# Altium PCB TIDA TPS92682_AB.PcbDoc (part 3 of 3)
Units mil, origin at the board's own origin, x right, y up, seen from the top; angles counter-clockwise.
Board outline 3149 x 2999 mil, 6 copper layers (Top Layer, Signal Layer 1, Signal Layer 2, Signal Layer 3, Signal Layer 4, Bottom Layer), stack 61.4 mil thick; 281 components, 181 nets, 796 pads, 814 vias.
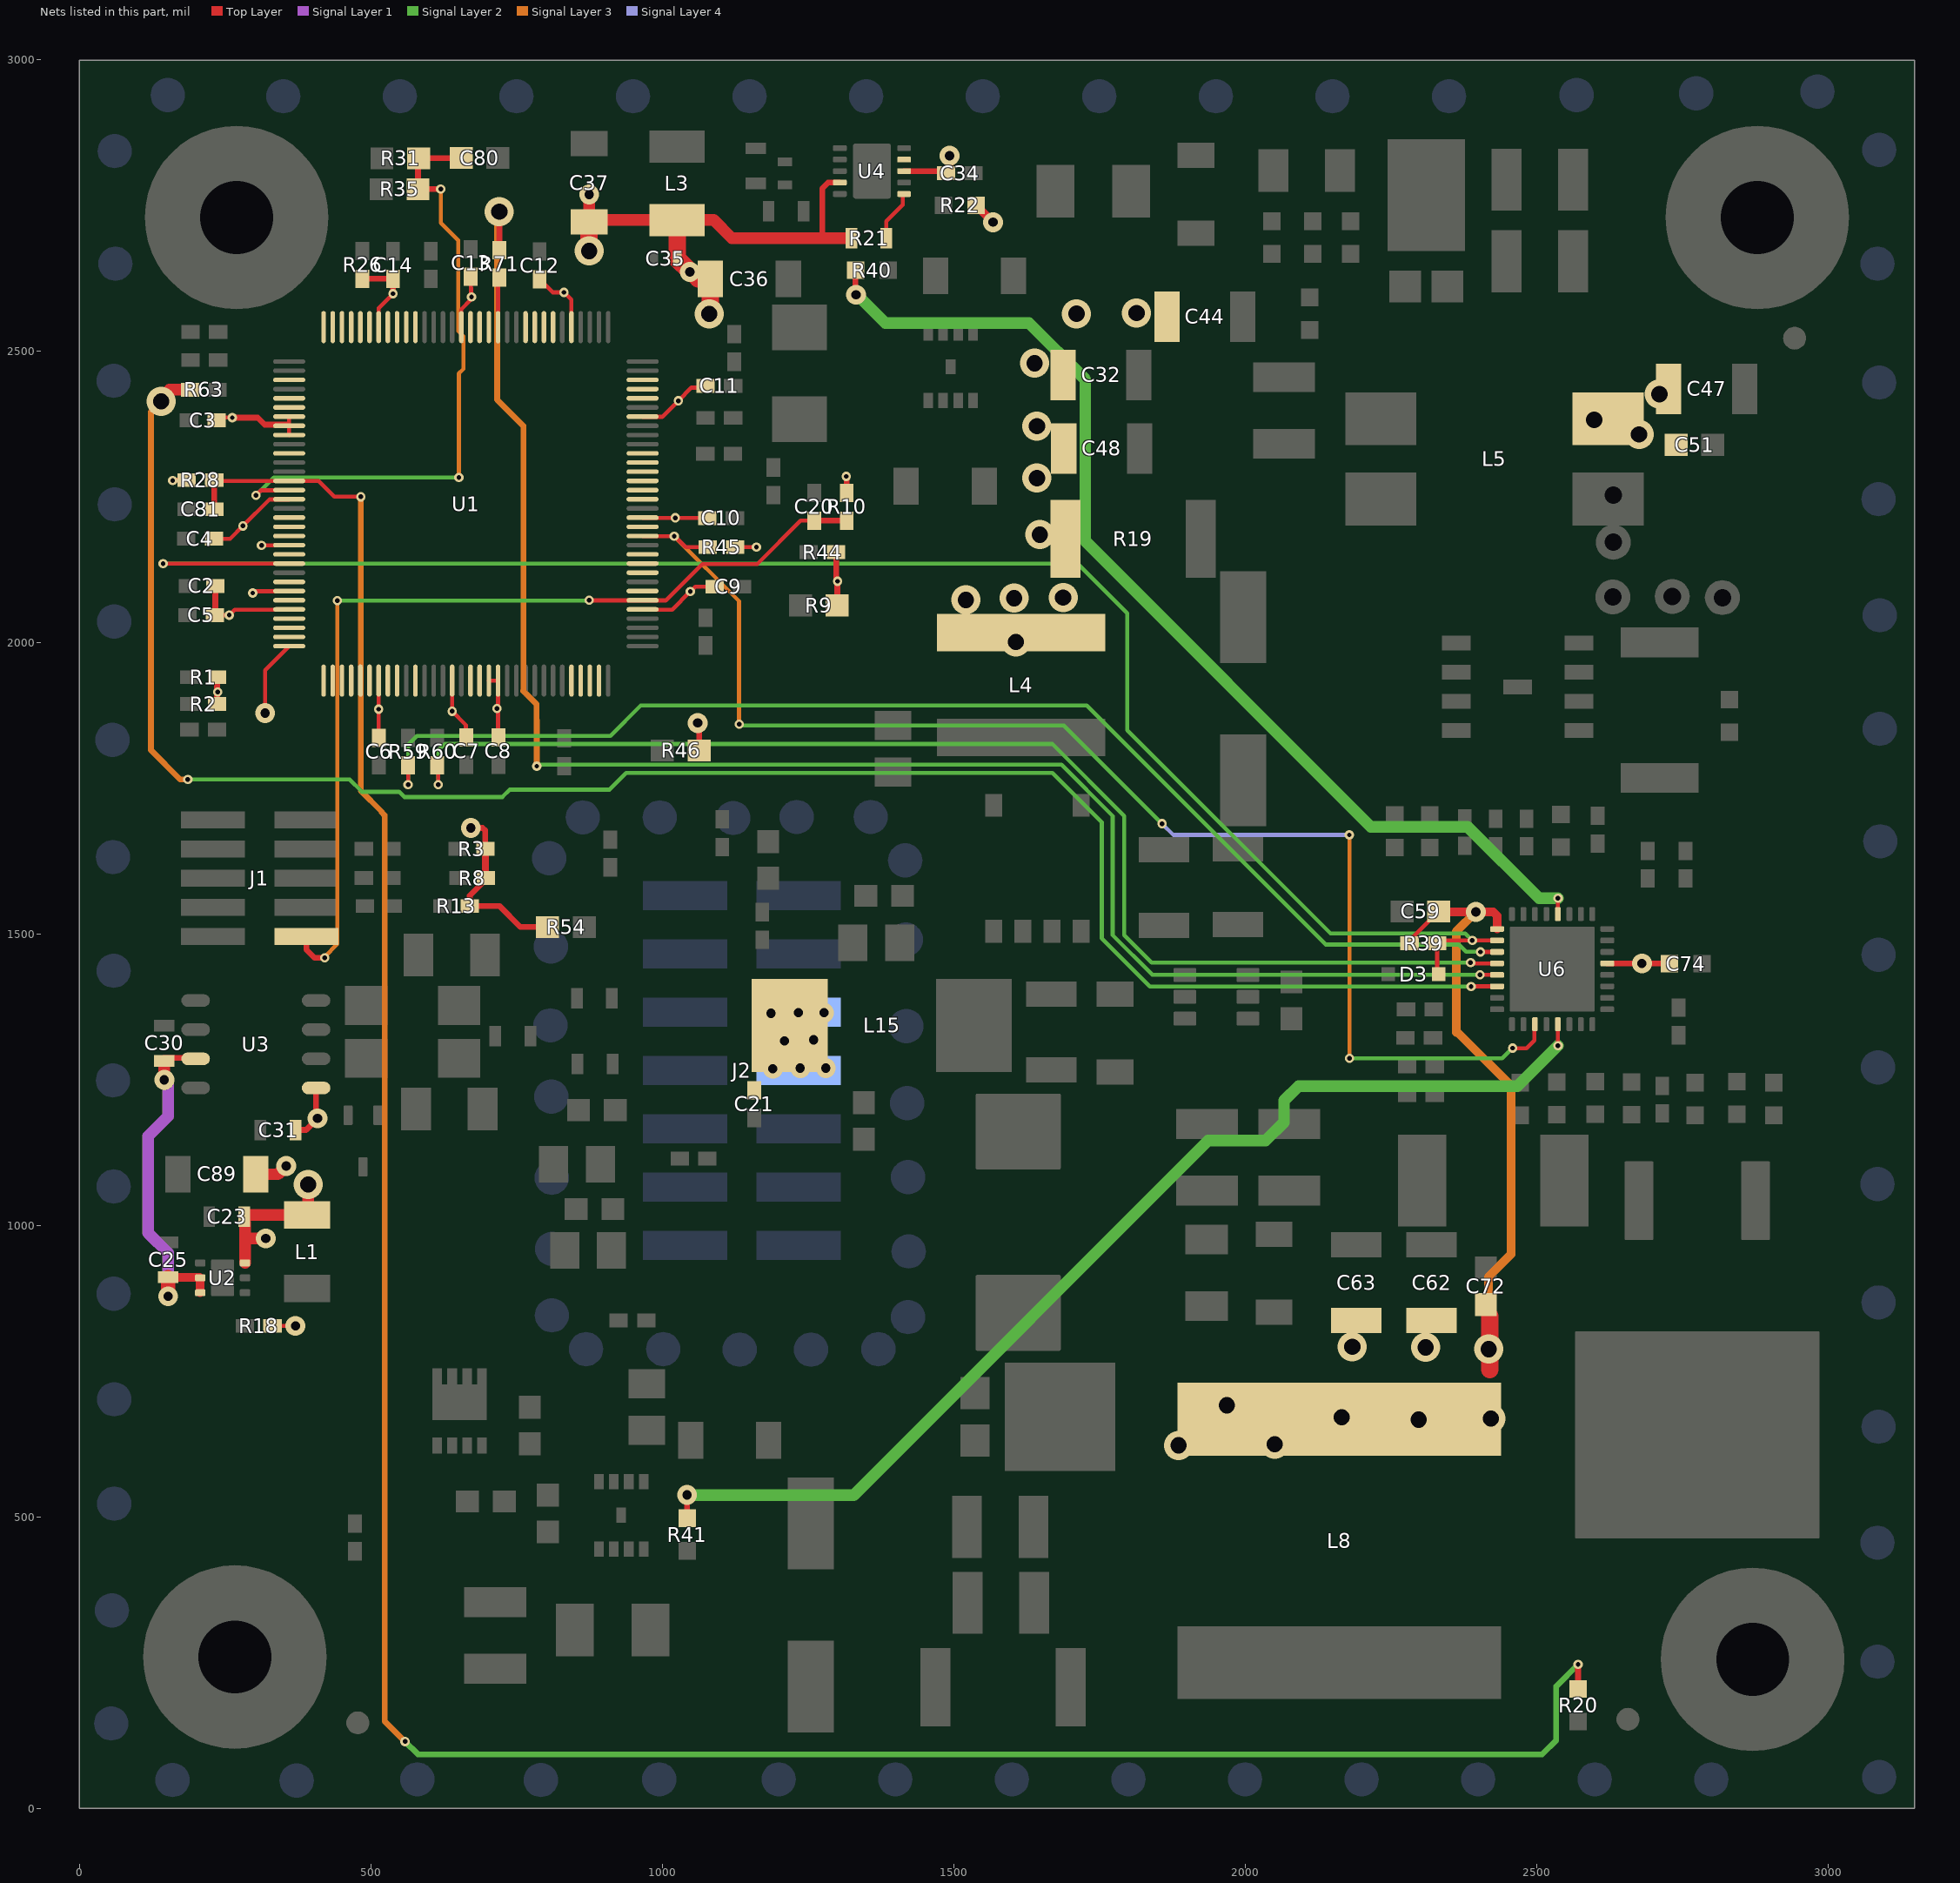
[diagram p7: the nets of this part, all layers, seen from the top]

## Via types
v1: diameter 16, hole 8, Top Layer to Bottom Layer, tented both sides, 458 vias
v2: diameter 50, hole 28, Top Layer to Bottom Layer, tented both sides, 188 vias
v3: diameter 34, hole 16, Top Layer to Bottom Layer, tented both sides, 85 vias
v4: diameter 16, hole 8, Top Layer to Bottom Layer, 33 vias
v5: diameter 34, hole 16, Top Layer to Bottom Layer, tented bottom, 30 vias
v6: diameter 19.68, hole 7.87, Top Layer to Bottom Layer, 18 vias
v7: diameter 34, hole 16, Top Layer to Bottom Layer, 2 vias

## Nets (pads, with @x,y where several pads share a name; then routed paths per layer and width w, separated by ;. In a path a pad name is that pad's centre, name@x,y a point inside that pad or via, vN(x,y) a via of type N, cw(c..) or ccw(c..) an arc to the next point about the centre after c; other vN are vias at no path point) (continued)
nFLT2: R45.1 U1.77 U6.11 | length 2358.5
  Top Layer w7: U1.77@966.49,2182.37 v1(1020.76,2182.37) 1022.02,2182.37 1040.76,2163.63 R45.1@1078.14,2163.63 ; v1@2459,1306.8 v1(2459,1304.4) 2459.4,1304 2483.08,1304 2496.68,1317.61 U6.11@2496.68,1345.27
  Signal Layer 2 w7: v1@1132,1857.68 1689.32,1857.68 v1(1857.69,1689.31) ; v1(2179.39,1287) 2179.67,1286.72 2441.32,1286.72 v1(2459,1304.4)
  Signal Layer 3 w7: v1(1020.76,2182.37) 1132,2071.13 v1@1132,1857.68 ; v1(2179.39,1287) v1@2179.39,1670
  Signal Layer 4 w7: v1(1857.69,1689.31) 1877,1670 v1(2179,1670)
  other v1: 1132.18,1859.96
nRST: R21.2 U4.6 | length 88.1
  Top Layer w7: R21.2@1384.76,2693.63 1384.76,2722.63 1412.76,2750.63 1412.76,2767.14 U4.6@1414.88,2769.26
PA2: U1.35
PA3: U1.36
PA4: U1.37
PA5: U1.38
PA6: U1.40
PA7: U1.41
PB3: U1.92
PB4: U1.121
PB5: U1.120
PC7: U1.22
PCB_Temp: C81.1 R20.2 R28.1 U1.14 | length 4664.4
  Top Layer w7: R28.1@231.58,2276.86 360.19,2276.86 410.59,2276.86 437.45,2250 v1(483,2250) ; R28.1@231.58,2278.67 R28.1@234.02,2276.23
  Top Layer w10: C81.1@231.58,2228.67 R28.1@231.58,2278.67 ; R20.2@2571.49,205.33 v1(2571.49,247.33)
  Signal Layer 2 w10: v1(559,115) 581,93 2510,93 2534,117 2534,209.84 v1(2571.49,247.33)
  Signal Layer 3 w10: v1(483,2250) 483,1746 519,1710 519,1708.72 524,1703.72 524,150 v1(559,115)
PD2: U1.3
PD4: U1.125
PD5: U1.126
PD6: U1.127
PD7: U1.128
PDRV1: R40.2 U6.28 | length 1864.9
  Top Layer w7: v3@1331.76,2597.63 v3(1332.76,2596.63) ; U6.28@2536.84,1534.25 v1@2536.84,1561.34
  Top Layer w10: v3@1331.76,2597.63 R40.2@1331.76,2638.63
  Signal Layer 2 w20: v3(1332.76,2596.63) 1334.37,2596.63 1383,2548 1629.4,2548 1726,2451.4 1726,2174.15 2216.15,1684 2382,1684 2504.5,1561.5 v1(2537,1561.5)
PDRV2: R41.2 U6.13 | length 1912.2
  Top Layer w7: U6.13@2536.78,1345.21 U6.13@2536.84,1345.27 2537,1345.11 v1(2537,1308.5)
  Top Layer w10: v3(1042.79,538) 1043,537.79 R41.2@1043,498
  Signal Layer 2 w20: v3(1042.79,538) 1043,537.79 1329,537.79 1936.97,1145.76 2035.41,1145.76 2067,1177.34 2067,1214.22 2091.78,1239 2467.5,1239 v1(2537,1308.5)
PE4: U1.123
PE5: U1.124
PF1: U1.43
PG0: U1.49
PG1: U1.50
PH0: U1.29
PH1: U1.30
PH2: U1.31
PH3: U1.32 | length 131.5
  Top Layer w7: v5(319,1879) 319,1952.21 U1.32@360.19,1993.39
PK0: U1.18
PK1: U1.19
PK2: U1.20
PK3: U1.21 | length 47.4
  Top Layer w7: v1(312.76,2166.63) U1.21@360.19,2166.62
PK4: U1.63
PK5: U1.62
PK6: U1.61
PK7: U1.60
PL0: U1.81
PL1: U1.82
PL2: U1.83
PL3: U1.84
PL4: U1.85
PL5: U1.86
PL6: U1.94
PL7: U1.93
PM0: U1.78
PM3: U1.75
PM4: U1.74
PM5: U1.73
PM7: U1.71
PN3: U1.110
PN4: U1.111
PN5: U1.112
POS_EN: U1.25
PP0: U1.118
PP1: U1.119
PP2: U1.103
PP3: U1.104
PP4: U1.105
PP5: U1.106
PQ0: U1.5
PQ1: U1.6
PQ2: U1.11
PQ3: U1.27
PWM1: R59.2 U6.3 | length 2173.5
  Top Layer w7: v1(564.23,1756) R59.2@564.23,1789.45 ; v1(2404,1469.29) U6.3@2432.51,1469.29
  Signal Layer 2 w7: v1(564.23,1756) 564.23,1824.88 579.35,1840 911.31,1840 963.31,1892 1728.3,1892 2138.3,1482 2366.84,1482 2379.34,1469.5 2403.79,1469.5 v1(2404,1469.29)
PWM2: R60.2 U6.4 | length 2189.8
  Top Layer w7: R60.2@614.23,1789.45 616,1787.68 v1(616,1756) ; v1(2387,1451) 2388.4,1449.6 U6.4@2432.51,1449.6
  Signal Layer 2 w7: v1(616,1756) 616,1814.84 627.16,1826 1669.33,1826 1793,1702.33 1793,1498 1840,1451 v1(2387,1451)
RST_N: C20.1 J1.10 R10.1 U1.70 | length 1612.7
  Top Layer w7: v1(874.76,2072.63) 875.25,2072.13 1006.26,2072.13 1068.76,2134.63 1163.33,2134.63 1237.8,2209.1 C20.1@1261,2209.1
  Top Layer w10: J1.10@389.7,1495.64 389.7,1473.3 404,1459 v1(421.03,1459) ; C20.1@1261,2209.1 R10.1@1316.73,2209.1
  Signal Layer 2 w7: v1(443,2072) 874.13,2072 v1(874.76,2072.63)
  Signal Layer 3 w7: v1(421.03,1459) 421.03,1461.03 443,1483 v1(443,2072)
SCLK: R63.1 U6.6 | length 3302
  Top Layer w7: v1@2388.23,1410.23 U6.6@2432.51,1410.23
  Top Layer w10: R63.1@185.89,2435.63 R63.1@190.96,2440.7
  Top Layer w20: v2(140.76,2413.63) 140.76,2419.63 154.76,2433.63 R63.1@190.14,2433.63
  Signal Layer 2 w7: v1(186.38,1765) 464,1765 485,1744 549,1744 558,1735 726,1735 738.5,1747.5 909.5,1747.5 938.5,1776.5 1669.5,1776.5 1754.24,1691.76 1754.24,1492.76 1837,1410 v1(2388,1410)
  Signal Layer 3 w10: v2(140.76,2413.63) 123,2395.87 123,1815.48 173.48,1765 v1(186.38,1765)
SSN: R71.1 U6.5 | length 2964.6
  Top Layer w7: v1(2403,1430) U6.5@2432.51,1429.92
  Top Layer w10: R71.1@720.76,2673.25 v2(720.76,2739)
  Signal Layer 2 w7: v1(785,1788) 787.5,1790.5 1685.03,1790.5 1773,1702.53 1773,1498 1841,1430 v1(2403,1430)
  Signal Layer 3 w10: v2(720.76,2739) 717,2735.24 717,2416.45 762,2371.45 762,1917 761.67,1917 784.76,1893.91 784.76,1867.24 785,1867 v1(785,1788)
SSN_1: R71.2 U1.109 | length 86.3
  Top Layer w7: U1.109@718.45,2540.64 718.45,2623.7 R71.2@720.76,2626.01
Sync: U4.9
TPS_EN: D3.1 R39.2 U1.23 U6.2 | length 3011.3
  Top Layer w7: v1@144,2135.13 U1.23@360.19,2135.13 ; v1(144,2135.35) v1@144.48,2136.52 ; D3.1@2329.62,1427.68 D3.1@2332.31,1425 ; D3.1@2332.31,1431 2329.62,1433.68 R39.2@2329.62,1484 2334.59,1488.97 U6.2@2432.51,1488.97
  Signal Layer 2 w7: v1(144,2135.35) 1712.65,2135.35 1798.1,2049.9 1798.1,1849.77 2146.87,1501 2378,1501 v1(2390,1489)
UART_0_RX: U1.33
UART_0_TX: U1.34
V3p3: C2.1 C3.1 C4.1 C5.1 C6.1 C7.1 C8.1 C9.1 C10.1 C11.1 C12.1 C13.1 C14.1 C23.1 C31.1 C35.1 C36.1 C37.1 C89.1 L1.1 L3.2 R1.2 R2.2 R3.2 R8.2 R9.1 R10.2 R13.2 R18.2 R21.1 R26.2 R28.2 R44.2 R45.2 R46.2 R54.2 U1.7 U1.8 U1.9 U1.16 U1.26 U1.28 U1.39 U1.47 U1.51 U1.52 U1.69 U1.79 U1.90 U1.101 U1.113 U1.122 U2.6 U3.5 U4.4 | length 3666.6
  Top Layer w7: C4.1@231,2178 258.85,2178 v1(280.85,2200) 326.21,2245.36 U1.16@360.19,2245.36 ; C5.1@233,2047 v1(257.38,2047) 266.76,2056.39 360.19,2056.39 U1.28@359.94,2056.63 ; C2.1@233,2095 233.62,2095.62 C2.1@241,2103 ; C3.1@236.96,2384.49 238.5,2386.03 305.76,2386.03 ; v1(297.69,2085) 300.58,2087.88 U1.26@360.19,2087.88 ; R18.2@331.62,828 v3(371,828) ; U1.9@360.19,2355.6 360.19,2371.35 U1.7@360.19,2386.03 ; C6.1@513.73,1836.09 v1(513.73,1885.72) U1.39@513.73,1934.34 ; U1.122@513.73,2540.64 513.73,2573.67 v1(538.34,2598.28) ; U1.47@639.71,1934.34 v1(639.71,1882.11) 663.34,1858.49 663.34,1838.08 C7.1@664.11,1837.31 ; U1.113@655.46,2540.64 655.46,2571.46 672.24,2588.24 672.18,2592.67 C13.1@671.76,2627.2 ; U1.51@702.71,1934.34 718.45,1934.34 v1@718.45,1887.63 ; v1(716.76,1886.63) 717.76,1887.63 v1@718.45,1887.63 ; C8.1@718.45,1835.82 v1@718.45,1887.63 ; C12.1@789.76,2623.2 812.32,2600.63 v1(831.76,2600.63) 844.44,2587.95 U1.101@844.44,2540.64 ; U1.69@966.49,2056.39 1017.23,2056.39 v1(1048.34,2087.49) 1048.62,2087.49 1056.76,2095.63 C9.1@1090.14,2095.63 ; U1.79@966.49,2213.87 v1(1022.76,2213.87) 1077.34,2213.87 C10.1@1077.71,2213.49 ; U1.90@966.49,2387.09 1000.17,2387.09 v1(1027.73,2414.66) 1050.34,2437.27 C11.1@1071.72,2437.27 ; R45.2@1125.38,2163.63 v1(1161.76,2163.63)
  Top Layer w8: v1@163.71,2278.67 R28.2@184.33,2278.67
  Top Layer w10: R28.2@183.38,2279.63 R28.2@184.33,2278.67 ; C5.1@233,2047 233.62,2047.62 233.62,2095.62 C2.1@233.62,2097 ; R2.2@236.38,1894.63 R1.2@236.38,1940.63 ; v1(262.55,2385.63) 305.76,2385.63 ; C23.1@281,1008 280.85,1008.15 280.85,1019.86 C23.1@282.71,1017.99 ; 305.76,2386.03 318.16,2373.63 357.9,2373.63 U1.8@360.19,2371.35 ; v3@355,1094.01 v3(355,1102) ; C31.1@371,1164 389.32,1164 v3(409,1183.68) 406.35,1186.34 U3.5@406.35,1236 ; R26.2@485.76,2624.01 538.2,2624.01 C14.1@538.34,2623.87 v1(538.34,2598.28) ; R13.2@671.74,1549.12 673.88,1551.26 R13.2@676.02,1549.12 ; v3(672,1682) 692,1682 696.67,1677.33 R3.2@696.67,1646 ; R8.2@697.67,1596 697.67,1593.44 670.12,1565.89 R13.2@670.12,1548.12 720.88,1548.12 756.95,1512.05 R54.2@803.5,1512.05 ; v5(1061,1862) 1063.5,1859.5 R46.2@1063.5,1815 ; 1275.76,2693.63 1274.76,2694.63 1274.76,2778.63 1285.07,2788.94 U4.4@1304.64,2788.94 ; v1@1298.62,2107.38 R44.2@1298.62,2155 ; R9.1@1300.5,2063.63 v1@1300.5,2105.5 ; v1(1316,2285) 1316.76,2284.24 R10.2@1316.76,2256.31
  Top Layer w12: C23.1@281,1008 C23.1@284.39,1004.61 ; R8.2@695.67,1594 696.67,1595 R3.2@696.67,1646
  Top Layer w20: C23.1@282.71,1017.99 L1.1@391,1017.99 ; U2.6@284.39,935.87 284.39,978 ; C23.1@284.39,1004.61 284.39,978 ; C89.1@303,1088 341,1088 v3(355,1102) ; v7(320,978) 284.39,978 ; L1.1@393,1017.99 v2(393,1070.5) ; v3(874.76,2768.63) C37.1@874.76,2721.7 877.69,2724.64 L3.2@1025.76,2724.64 1088.75,2724.64 1119.76,2693.63 1275.76,2693.63 R21.1@1324.76,2693.63 ; C36.1@1061.76,2623.63 C36.1@1082.83,2623.63 ; v2(1080.76,2563.63) 1080.76,2569.63 v2@1082.83,2571.7
  Top Layer w30: v2(874.76,2671.63) C37.1@874.76,2721.7 ; C35.1@1024.76,2658.63 v3(1047.76,2635.63) ; C35.1@1025.76,2659.63 L3.2@1025.76,2724.64 ; C35.1@1026.57,2658.81 C36.1@1061.76,2623.63 ; v2@1082.83,2571.7 C36.1@1082.83,2623.63
  other v1: 237.76,1915.13 1301,2105 160.38,2278 673.08,2592.68
V5p0: C25.1 C30.1 U2.2 U2.3 U3.3 | length 603.7
  Top Layer w10: C30.1@145.58,1282.64 150.58,1287.64 U3.3@199.65,1287.64
  Top Layer w15: C25.1@152.42,911.36 U2.2@206.53,911.36 ; U2.3@207.61,884.69 U2.2@207.61,910.28
  Top Layer w20: C30.1@145.58,1282.64 146,1282.22 v3(146,1250)
  Top Layer w25: v3(152.42,878.58) C25.1@152.42,911.36
  Signal Layer 1 w10: v3(146,1250) v3@152.42,1243.58
  Signal Layer 1 w20: v3(152.42,878.58) 152.42,953.28 118.42,987.28 118.42,1153.42 152.42,1187.42 v3@152.42,1243.58
VBATT_Filt: C32.1 C34.1 C44.1 C47.1 C48.1 C51.2 C59.2 C62.1 C63.1 C72.2 L4.2 L5.2 L8.1 R19.2 R22.2 R39.1 U4.8 U6.1 | length 1264
  Top Layer w7: R39.1@2282.38,1484 2282.38,1488.88 C59.2@2332.5,1539 C59.2@2333.54,1537.96
  Top Layer w10: U4.8@1415.12,2808.63 1483.41,2808.63 C34.1@1487.14,2804.9
  Top Layer w12: C34.1@1487.14,2804.9 1493,2810.75 v3(1493,2835) ; R22.2@1538.76,2749.9 R22.2@1538.76,2753.27
  Top Layer w15: R22.2@1538.76,2749.9 v3(1567.76,2720.9) ; C59.2@2333.54,1537.96 v3(2396,1537.96) 2425.84,1537.96 2432.51,1531.29 U6.1@2432.51,1508.66
  Top Layer w30: 2420,753 2420,844.5
  Signal Layer 3 w15: v3(2396,1537.96) 2362.23,1504.19 2362.23,1331.12 2364.88,1331.12 2456.38,1239.62 2456.38,950.92 2418,912.54 v2(2418,788)
  other v2: 1886,623 2051,625 2298,667 2422,669 2166,671 1969,691.83 2310,791 2184,792 1607,2001 1521,2073 1604,2076 1688,2077 1648,2185 1643,2282 2676,2357 1643,2371 2599,2382 2711,2426 1639,2479 1711,2564 1814,2565
VCC: C74.1 U6.21 | length 110.3
  Top Layer w10: U6.21@2621.49,1449.6 2689,1449.6 2729.1,1449.6 C74.1@2731,1451.5
  other v3: 2681,1449.6
VIN+: C21.1 J2.5 J2.7 L15.1
  other v3: 1190,1269 1237,1270 1281,1270 1210.07,1316.68 1260.07,1318.68 1187,1364 1234,1365 1278,1365
VIN_ADC: C80.2 R31.1 R35.2 U1.15 | length 1100.5
  Top Layer w7: v1(303.48,2252.63) 311.96,2261.11 U1.15@360.19,2261.11
  Top Layer w10: v1(620.2,2777.63) R35.2@581.25,2777.63 581.25,2829.63 R31.1@582.25,2830.63 655.09,2830.63 C80.2@655.46,2831
  Signal Layer 2 w7: v1(303.48,2252.63) 333.85,2283 v1(651.37,2283)
  Signal Layer 3 w7: v1(620.2,2777.63) 620.2,2719.91 650.1,2690.01 650.1,2687 650.1,2534.23 659.27,2525.07 659.27,2469.27 651.37,2461.37 v1(651.37,2283)
pads on no net: Designator11.1@3090,1659 Designator12.1@3089,1852 Designator13.1@3087,1464.56 Designator14.1@1418.83,1342 Designator15.1@1418,1490.38 Designator16.1@1417,1626.19 Designator17.1@1357.92,1700.69 Designator18.1@1231,1700.69 Designator19.1@1121.96,1699 Designator20.1@996,1700.02 Designator21.1@864,1700.02 Designator22.1@806.26,1630 Designator23.1@809.14,1478.5 Designator24.1@808.42,1343.32 Designator25.1@810,1221 Designator26.1@810.69,1082 Designator27.1@811.52,960 Designator28.1@811,846 Designator29.1@869.45,788 Designator30.1@1002,788 Designator31.1@1133,787.2 Designator32.1@1255.46,787.2 Designator33.1@1371,788 Designator34.1@1422,843 Designator35.1@1423,955.7 Designator36.1@1422,1083 Designator37.1@1420.48,1210 Designator38.1@3088,54 Designator39.1@3085,252 Designator40.1@3085,456 Designator41.1@3087,654.98 Designator42.1@3087,868 Designator43.1@3085,1071.26 Designator44.1@3086,1271.24 Designator45.1@3089,2046.76 Designator46.1@3087,2246 Designator47.1@3088,2446 Designator48.1@3085,2649.81 Designator49.1@3088,2845 Designator50.1@2982,2945 Designator51.1@2774,2942 Designator52.1@2568.87,2939 Designator53.1@2350,2937 Designator54.1@2150,2937 Designator55.1@1950,2937 Designator56.1@1750,2937 Designator57.1@1550,2937 Designator58.1@1350,2937 Designator59.1@1150,2937 Designator60.1@950,2937 Designator61.1@750,2937 Designator62.1@550,2937 Designator63.1@350,2937 Designator64.1@152,2939 Designator65.1@61,2843 Designator66.1@62,2649.81 Designator67.1@59,2449 Designator68.1@61,2237 Designator69.1@60,2036 Designator70.1@57,1833 Designator71.1@58,1632 Designator72.1@59,1437 Designator73.1@58,1249 Designator74.1@59,1067 Designator75.1@59,883 Designator76.1@60,702 Designator77.1@60,523 Designator78.1@56,340 Designator79.1@55,146 Designator80.1@160,49 Designator81.1@373,48 Designator82.1@580,50 Designator83.1@791.94,49 Designator84.1@995,50 Designator85.1@1200,50 Designator86.1@1400,50 Designator87.1@1600,50 Designator88.1@1800,50 Designator89.1@2000,50 Designator90.1@2200,50 Designator91.1@2400,50 Designator92.1@2600,50 Designator93.1@2800,50 FID1.1 FID2.1 FID3.1 J1.7 LBL1.0 U1.65 U1.67 U1.72 U1.102 U2.7@246,892.57 U2.7@246,928 U4.11@1350.16,2748.39 U4.11@1350.16,2868.87 U4.11@1360,2783.83 U4.11@1360,2833.43 U4.11@1369.84,2748.39 U4.11@1369.84,2868.87

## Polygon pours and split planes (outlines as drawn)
GND on Top Layer "Top Layer-No Net 27" (solid, pour order 220): 2537,2601 2630,2508 2734.42,2508 2797.45,2444.97 2797.45,2294 2555.83,2294 2555.83,2034 2619.26,2034 2639.26,2014 2640,2014 2640,1941 2642,1939 2644,1941 2805,1941 2922,1941 2922,2441.85 2639.26,2742.81 2639.26,2847.15 2588.85,2847.15 2537,2847.15
NetC61_2 on Top Layer "Top Layer-NetC61_2" (solid, pour order 302): 1563,1012.71 1760,1012.71 1760,767 1582,767 1582,294.87 1494.36,294.87 1434.11,353.68 1339.97,353.68 1216.69,353.68 1216.69,571.1 1450.76,761.11 1450.76,1012.71
NetC78_1 on Top Layer "Top Layer-NetC78_1" (solid, pour order 298): 606,668 606,673 606,990.43 860,990.43 860,926 787,926 716.76,855.76 716.76,789.24 793,713 792,712 792,668
LB_ANODE on Top Layer "LB_ANODE" (solid, pour order 260): 973,990.01 1013.37,990.01 1114.93,990.01 1114.93,823.52 1040.5,823.52 1040.5,701.01 943.58,701.01 943.58,869.21 973,898.63
NetC40_2 on Top Layer "Top Layer-NetC40_2" (solid, pour order 284): 1503,1264.94 1600,1264.8 1600,1357 1817,1357 1817,1418.89 1684,1418.89 1684,1523.5 1503,1523.5
DRL+ on Top Layer "Top Layer-DRL+" (solid, pour order 290): 1159,1538.22 1159,1545 1159,1623 1218,1623 1240,1645 1240,1805 1431.5,1805 1431.5,1613.05 1306,1613.05 1306,1538.22
DRL- on Top Layer "Top Layer-DRL-" (solid, pour order 288): 1160.54,1440 1357,1440 1357,1577 1330,1577 1330,1519 1299.5,1519 1299.5,1499 1160,1499
NetC42_1 on Top Layer "Top Layer-NetC42_1" (solid, pour order 286): 1499,1562.18 1754,1562.18 1754,1613 1986,1613 2030,1613 2030,1671 1816.62,1671 1761,1726.62 1761,1869 1499,1869
VIN+ on Top Layer "Top Layer-VIN+" (solid, pour order 282): 1146,1423 1146,1230 1306,1230 1306,1423
NetC56_1 on Top Layer "Top Layer-NetC56_1" (solid, pour order 266): 1570,2496 1570,2397.47 1550.84,2378.32 1456.31,2378.31 1443,2365 1443,1834.72 1365.27,1834.72 1361,2496
GND on Top Layer "Top Layer-GND 1" (solid, pour order 276): 674.32,640 674.32,506.3 540.19,506.3 538.34,506.3 535.55,506.3 535.55,640
no net on Top Layer "Top Layer-No Net 2" (solid, pour order 274): 568.5,637
HB_LB_TAP on Top Layer "Top Layer-HB_LB_TAP" (solid, pour order 272): 966,1092.29 967.05,1092.29 1113,1092.29 1113,1032.29 978.25,1032.29 952.49,990.95 952.49,940.01 930.78,918.3 886,918.3 886,1046.5 912.5,1046.5 958.29,1092.29
HB_CATHODE on Top Layer "Top Layer-HB_CATHODE" (solid, pour order 270): 862,1072.91 862,1145 895,1145 895,1219 1112,1219 1112,1136 975.88,1136 917,1072.91
NetC64_1 on Top Layer "Top Layer-No Net" (solid, pour order 76): 2999,897.83 2999,131.78 1610,131.78 1610,556 1856,556 2476,556 2476,897.83
NetC70_1 on Top Layer "TOP_LAYER_NETC70_1_P156" (solid, remove dead copper, pour order 156): 855,673 855,483 1005,483 1005,573 1071,573 1071,673
no net on Top Layer "Top Layer-No Net 9" (solid, pour order 248): 491.69,394
NetC41_1 on Top Layer "Top Layer-No Net 16" (solid, pour order 198): 1959,1962.54 1959,2047.22 1898,2108.22 1898,2244.92 1949,2244.92 2054.54,2134.63 2054.54,1962.54
VBATT_Filt on Top Layer "Top Layer-No Net 15" (solid, pour order 178): 1472,1970 1760,1970 1760,2502 1776,2518 1885,2518 1885,2602 1882,2605 1881,2604 1687,2604 1601,2518 1601,2111 1472,2111
NetQ3_1 on Top Layer "Top Layer-No Net 23" (solid, pour order 144): 2548,1760 2551,1760 2766,1760 2766,1827 2766,1828 2766,1829 2766,1839 2661,1839 2598,1902 2598,1962 2548,1962
NetC69_1 on Top Layer "Top Layer-No Net 17" (solid, pour order 130): 951,458 951,390.39 929.59,362 894,362 894,261 797,261 797,328 657,328 657,428.84 854.43,428.84 883.59,458
NetC67_2 on Top Layer "Top Layer-No Net 10" (solid, pour order 108): 1715,895.61 1874.46,1085 2129,1085 2129,1022 1974.38,1022 1974.38,912 1885,912 1835.05,841.85 1835.05,579.43 1715,579.43
VBATT_Filt on Top Layer "Top Layer-No Net 1" (solid, pour order 78): 1860,744 1860,584 2456,584 2456,865 2138,865 2138,744
NetQ7_3 on Top Layer "Top Layer-No Net 3" (solid, pour order 82): 2507,1128 2507,972.36 2766,972.36 2766,1128
NetC49_2 on Top Layer "Top Layer-No Net 6" (solid, pour order 88): 2011,2394 2168,2394 2168,2338 2375,2338 2375,2639 2248,2639 2248,2584 2145,2481 2011,2481
NetC53_2 on Top Layer "Top Layer-No Net 7" (solid, pour order 90): 2475,2865 2475,2592.28 2390.72,2592.28 2390.72,2661 2220,2661 2220,2694 2090,2694 2090,2775 2090,2865
VBATT_Filt on Top Layer "Top Layer-No Net 8" (solid, pour order 94): 2559,2432 2640,2432 2681,2473 2754,2473 2754,2319 2560,2319 2559,2318
NetC49_1 on Top Layer "Top Layer-No Net 5" (solid, pour order 116): 2014,2367 2015,2366 2120.13,2366 2120.13,2313 2350,2313 2519.54,2313 2519.54,1776 2171,1776 2171,2049.9 2014,2212.56
NetC55_2 on Top Layer "Top Layer-No Net 14" (solid, pour order 118): 1473,2517.26 1565,2517.26 1565,2579 1473,2579
NetC78_2 on Top Layer "TOP_LAYER_NETC78_2_P158" (solid, remove dead copper, pour order 158): 687,651 794,651 807,638 807,598 829.7,575.3 829.7,511 771,511 756,496 719,496 719,546 687,578
V3p3 on Top Layer "TOP_LAYER_V3P3_P162" (solid, remove dead copper, pour order 162): 325.36,2386.63 324.76,2386.03 324.76,2356.47 328.6,2352.63 390.76,2352.63 390.76,2386.63
GND on Top Layer "Top Layer-No Net 24" (solid, pour order 166): 1327.43,2762.6 1391.51,2762.24 1392.24,2762.96 1392.24,2888 1327.43,2888
NetC85_1 on Top Layer "Top Layer-No Net 26" (solid, pour order 188): 1884,877 1884,770 2089,770 2089,878 1883,878
GND on Top Layer "Top Layer-GND" (solid, pour order 304): 1513,1235 1624,1235 2193.66,1235 2236.66,1192 2429,1192 2429,939.28 2147.64,939.28 2018,939.28 2018,1007 2018,1009.8 2018.8,1009.8 2151.04,1009.8 2151.04,1135 1830.29,1135 1758.9,1032.34 1513,1032.34
GND on Top Layer "Top Layer-GND 2" (solid, pour order 306): 1146.07,1193.5 1312,1193.5 1312,941 1150,941 1148,943
GND on Signal Layer 1 "SIGNAL_LAYER_1_GND_P330" (solid, remove dead copper, pour order 330): -7,2996 -4,2999 3137,2999 3137,7 3140,4 3,4
V3p3 on Signal Layer 1 "Signal Layer 1-V3p3" (solid, pour order 324): 115.01,2898 1418.83,2898 1418.83,1764.48 1374.79,1764.48 715,1764.48 715,717.37 721.37,711 940,711 940,92 115.01,92
NetC49_1 on Signal Layer 1 "Signal Layer 1-NetC49_1" (solid, pour order 308): 2014,2365.59 2014.41,2366 2120.13,2366 2120.13,2313 2519.54,2313 2519.54,1776 2171,1776 2171,2049.9 2014,2212.56
NetC85_1 on Signal Layer 1 "SIGNAL_LAYER_1_NETC85_1_P146" (solid, remove dead copper, pour order 146): 2122,888.03 1556.01,888.03 1063.98,396 941,396 941,210 1058.55,210 1613.55,765 2122,765
NetC64_1 on Signal Layer 1 "Signal Layer 1-No Net" (solid, pour order 190): 1630,556 1639,556 2472,556 2472,928 2472,1101 3034,1101 3034,90 2975,90 1608,90 1608,556
GND on Signal Layer 2 "SIGNAL_LAYER_2_GND_P332" (solid, remove dead copper, pour order 332): 21,0 3140,0 3149,9 3149,2999 0,2999
NetC49_1 on Signal Layer 2 "Top Layer-No Net 5" (solid, pour order 206): 2014,2366 2019,2366 2120.13,2366 2120.13,2313 2350,2313 2519.54,2313 2519.54,1772 2170.83,1772 2170.83,1955 2170.83,2049.9 2014,2212.56
NetC64_1 on Signal Layer 2 "Signal Layer 2-No Net" (solid, pour order 192): 1610,556 2471.19,556 2471.19,1100 3033,1100 3033,90 1634,90 1610,90
no net on Signal Layer 2 "Signal Layer 2-No Net 1" (solid, pour order 316): 1154,1399
GND on Signal Layer 3 "SIGNAL_LAYER_3_GND_P342" (solid, remove dead copper, pour order 342): 0,2999 3149,2999 3149,0 0,0
VBATT_Filt on Signal Layer 3 "SIGNAL_LAYER_3_VBATT_FILT_P340" (solid, remove dead copper, pour order 340): 1435,2909 1435,1295.24 1433,1293.24 3042,1293.24 3042,2909
NetC64_1 on Signal Layer 3 "Signal Layer 3-No Net" (solid, pour order 194): 1634,556 2472,556 2472,1101 3034,1101 3034,91 1610,91 1610,556
NetC49_1 on Signal Layer 3 "Top Layer-No Net 5" (solid, pour order 204): 2014,2367 2015,2366 2120.13,2366 2120.13,2313 2350,2313 2519.54,2313 2519.54,1776 2170,1776 2170,2049.9 2014,2212.56
GND on Signal Layer 4 "SIGNAL_LAYER_4_GND_P336" (solid, remove dead copper, pour order 336): 0,-7 0,2999 3149,2999 3149,9 3144,4
NetC64_1 on Signal Layer 4 "Signal Layer 4-No Net" (solid, pour order 196): 1610,556 2472,556 2472,1101 3034,1101 3034,91 1610,91
NetC49_1 on Signal Layer 4 "Top Layer-No Net 5" (solid, pour order 208): 2014,2367 2015,2366 2120.13,2366 2120.13,2313 2350,2313 2519.54,2313 2519.54,1776 2171,1776 2171,1948 2171,2049.9 2014,2212.56
GND on Bottom Layer "BOTTOM_LAYER_GND_P338" (solid, remove dead copper, pour order 338): 0,2999 3149,2999 3149,5 3144,0 3137,7 7,7
NetC64_1 on Bottom Layer "Top Layer-No Net" (solid, pour order 200): 3009,1101 3009,127 1610,127 1610,556 1856,556 2471.19,556 2471.19,1101
NetC49_1 on Bottom Layer "Top Layer-No Net 5" (solid, pour order 202): 2014,2367 2015,2366 2120.13,2366 2120.13,2313 2350,2313 2519.54,2313 2519.54,1782 2519.54,1776 2170,1776 2170,2049.9 2014,2212.56
VIN+ on Bottom Layer "Bottom Layer-VIN+" (solid, pour order 320): 1161.76,1390 1304.5,1390 1306,1391.5 1307.24,1390.26 1307.24,1242 1163,1242 1161.76,1243.24
no net on M1 Board Outline (solid): 384.99,781.24

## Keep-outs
Keep-Out Layer:
  text ".Layer_Name" at -282,-949.49 h60

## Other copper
Top Layer:
  rectangle net GND: 1612.88,1244.5 1855.39,1332
  rectangle net GND: 1818,1491.68 2101.24,1594
  rectangle net NetC56_1: 1361.21,2404 1571,2496.75
  rectangle net NetC70_1: 854,484 1006,584
  rectangle net GND: 10,2900 3135,2987
  rectangle net GND: 10,11 3135,86
  region net GND: 3135,18 3135,2980 3040,2980 3040,18
  region net GND: 107,25 107,2987 10,2987 10,25
  rectangle net V3p3: 1029.43,2593 1104.29,2656.04
  rectangle net GND: 1445,2596.91 1497,2708
  region net NetC42_1: 1594,1697.62
  pour cut-out: 494,391
  text ".Layer_Name" at -282,-949.49 h60
Signal Layer 1:
  rectangle net NetC67_2: 1626.48,574 1829,758
  rectangle net NetC53_2: 2233.12,2661 2390.72,2865.61
Signal Layer 2:
  rectangle net NetC67_2: 1626.48,574 1829,758
  rectangle net NetC53_2: 2233.12,2661 2390.72,2865.61
Signal Layer 3:
  rectangle net NetC67_2: 1626.48,574 1829,758
  rectangle net NetC53_2: 2233.12,2661 2390.72,2865.61
Signal Layer 4:
  rectangle net NetC67_2: 1626.48,574 1829,758
  rectangle net NetC53_2: 2233.12,2661 2390.72,2865.61
Bottom Layer:
  rectangle net NetC67_2: 1626.48,574 1829,758
  rectangle net NetC53_2: 2233.12,2661 2390.72,2865.61
  rectangle net GND: 10,11 3135,86
  region net GND: 3135,18 3135,2980 3046,2980 3046,18
  region net GND: 104,25 104,2987 10,2987 10,25
  rectangle net GND: 10,2900 3135,2987
  rectangle net GND: 749.59,734 879.59,1742
  rectangle net GND: 1357,734 1487,1743
  rectangle net GND: 749.59,734 1473,838
  rectangle net GND: 749.59,1639 1473,1743
  text ".Layer_Name" at -282,-949.49 h60

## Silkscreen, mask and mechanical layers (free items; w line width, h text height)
Top Overlay:
  text "1" at 217,1745 h50
  text "10" at 402.61,1418.93 h50
  text ".Layer_Name" at -282,-949.49 h60
Bottom Overlay:
  text "TIDA-050029" at 2428,710 h72.83
  text ".Layer_Name" at -282,-949.49 h60
Top Paste:
  text ".Layer_Name" at -282,-949.49 h60
Bottom Paste:
  text ".Layer_Name" at -282,-949.49 h60
Top Solder:
  text ".Layer_Name" at -282,-949.49 h60
  text ".Layer_Name" at -282,-949.49 h60
Bottom Solder:
  text ".Layer_Name" at -282,-949.49 h60
Drill Guide:
  text ".Layer_Name" at -282,-949.49 h60
M1 Board Outline:
  the board outline again, w10
  text ".Layer_Name" at -282,-949.49 h60
M2 Board Dimensions:
  rectangle: -734,-491 -359,-366
  rectangle: -859,-366 -734,-241
  lines w7: -859,-366 141,-366 ; -734,-491 -734,-241 ; -609,-491 -609,-241 ; -359,-491 -359,-241 ; -109,-491 -109,-241 ; -859,-491 -859,-241 141,-241 141,-491 -859,-491
  text ".Layer_Name" at -282,-949.49 h60
M3 3D STEP Top:
  text ".Layer_Name" at -282,-949.49 h60
M4 3D STEP Bottom:
  text ".Layer_Name" at -282,-949.49 h60
M5 Assembly Top:
  lines w10: -1151,-1021.17 5449,-1021.17 ; -1151,-817.83 5451,-817.83 ; -1151,-614.5 -1151,-1224.5 2854,-1224.5 5451,-1224.5 5451,-614.5 -1150.5,-614.5 -1150.5,-1224.5 425,-1224.5 ; 1314,-1224.5 1314,-614.5 ; 2581,-817.83 2581,-614.5 ; 3421,-817.83 3421,-614.5 ; 4043,-1231 4043,-1028.17
  text "COMPONENTS MARKED 'DNP' SHOULD NOT BE POPULATED." at 294.5,-409.5 h60
  text "ASSEMBLY VARIANT:" at 294,-525 h60
  text ".VariantName" at 1330,-525 h60
  text "PCB VIEWED FROM TOP SIDE" at -1087.5,-746.67 h60
  text "BOARD #:" at 1389,-746.67 h60
  text ".PRJ_Number" at 1934.5,-746.67 h60
  text "REV:" at 2779,-746.67 h60
  text ".PCB_Rev" at 3070.5,-746.67 h60
  text "SVN REV:" at 3617,-746.67 h60
  text ".VersionControl_RevNumber" at 4123,-746.67 h60
  text "TID #:" at 1389,-950 h60
  text ".TID" at 1934.5,-950 h60
  text "PLOT NAME =" at -1087.5,-1155.34 h60
  text ".plot_File_Name" at -282,-1155.34 h60
  text "GENERATED    :" at 1391,-1155.34 h60
  text ".Print_Date" at 2260.5,-1155.34 h60
  text ".Print_Time" at 2989.5,-1155.34 h60
  text "TEXAS INSTRUMENTS" at 4254,-1155.34 h60
M6 Assembly Bottom:
  lines w10: -1151.5,-818.33 5450.5,-818.33 ; -1149.5,-1021.67 5450.5,-1021.67 ; 256.5,-1231.5 256.5,-1028.67 ; 878.5,-818.33 878.5,-615 ; 1718.5,-818.33 1718.5,-615 ; 2985.5,-1225 2985.5,-615 ; 3874.5,-1225 5450,-1225 5450,-615 -1151.5,-615 -1151.5,-1225 1445.5,-1225 5450.5,-1225 5450.5,-615
  text "COMPONENTS MARKED 'DNP' SHOULD NOT BE POPULATED." at 5243,-409 h60
  text ".VariantName" at 4199,-525 h60
  text "ASSEMBLY VARIANT:" at 5238,-525 h60
  text ".VersionControl_RevNumber" at 176.5,-747.17 h60
  text "SVN REV:" at 682.5,-747.17 h60
  text ".PCB_Rev" at 1229,-747.17 h60
  text "REV:" at 1520.5,-747.17 h60
  text ".PRJ_Number" at 2365,-747.17 h60
  text "BOARD #:" at 2910.5,-747.17 h60
  text "PCB VIEWED FROM BOTTOM SIDE" at 5387,-747.17 h60
  text ".TID" at 2365,-950.5 h60
  text "TID #:" at 2910.5,-950.5 h60
  text "TEXAS INSTRUMENTS" at 45.5,-1155.84 h60
  text ".Print_Time" at 1310,-1155.84 h60
  text ".Print_Date" at 2039,-1155.84 h60
  text "GENERATED    :" at 2908.5,-1155.84 h60
  text ".plot_File_Name" at 4581.5,-1155.84 h60
  text "PLOT NAME =" at 5387,-1155.84 h60
M9 Title Sheet:
  drawing of 57 lines, arcs and shapes, not listed
  text "1" at -119.16,7945.5 h70
  text "2" at 2376.5,7945.5 h70
  text "3" at 4865.84,7945.5 h70
  text "4" at 7372.51,7945.5 h70
  text "5" at 9871.5,7945.5 h70
  text "6" at 12376.5,7945.5 h70
  text "A" at -1275.5,6802.5 h70
  text "A" at 13524.5,6802.5 h70
  text "B" at -1275.5,4422.5 h70
  text "B" at 13524.5,4422.5 h70
  text "C" at -1275.5,2047.5 h70
  text "C" at 13524.5,2047.5 h70
  text "PROJECT TITLE:" at 10484.5,186.5 h45
  text ".PRJ_Title" at 10534.5,53.17 h70
  text "DESIGNED FOR:" at 10484.5,-114.5 h45
  text ".PRJ_Customer" at 10534.5,-254.5 h70
  text "D" at -1275.5,-322.5 h70
  text "D" at 13524.5,-322.5 h70
  text "FILE NAME:" at 10484.5,-414.5 h45
  text ".PCB_File_Name_No_Path" at 10534.5,-534.5 h70
  text "Texas Instruments (TI) and/or its licensors do not warrant the accuracy or completeness of this specification" at 5515,-696.34 h45
  text "ENGINEER:" at 10484.5,-704.5 h45
  text "LAYOUT BY:" at 11989.5,-704.5 h45
  text "or any information contained therein. TI and/or its licensors do not warrant that this design will meet" at 5470.01,-809 h45
  text ".PRJ_Engineer" at 10534.5,-859.49 h70
  text ".PCB_Layout" at 12040,-859.49 h70
  text "the specifications, will be suitable for your application or fit for any particular purpose, or will operate in" at 5470.01,-921.67 h45
  text ".Layer_Name" at -282,-949.49 h60
  text "ALTIUM DESIGNER VERSION:" at 11989.5,-1014.5 h45
  text "an implementation. TI and/or its licensors do not warrant that the design is production worthy. You should" at 5470.01,-1034.33 h45
  text "completely validate and test your design implementation to confirm the system functionality for your application." at 5515,-1147 h45
  text ".print_Scale" at 10534.5,-1147.83 h70
  text ".Application_BuildNumber" at 12040,-1147.83 h70
  text "1" at -119.16,-1354.5 h70
  text "2" at 2376.5,-1354.5 h70
  text "3" at 4865.84,-1354.5 h70
  text "4" at 7372.51,-1354.5 h70
  text "5" at 9871.5,-1354.5 h70
  text "6" at 12376.5,-1354.5 h70
M10 Fab Notes:
  drawing of 189 lines, arcs and shapes, not listed
  text "DESIGN INFORMATION" at 11523.02,6265.17 h60
  text "MIN. TRACK WIDTH:" at 10878.46,6133.05 h60
  text "6" at 11974.7,6133.05 h60
  text "MIL" at 12129.46,6133.05 h60
  text "MIN. CLEARANCE:" at 10878.46,6008.92 h60
  text "0.2" at 11914.7,6008.93 h60
  text "mm" at 12129.46,6008.92 h60
  text "MIN. VIA PAD SIZE:" at 10878.46,5884.8 h60
  text "16" at 11944.71,5884.8 h60
  text "MIL" at 12129.46,5884.8 h60
  text "0.05mm (2MIL)" at 11573.46,5754.9 h60
  text "MINIMUM ANNULAR RING" at 10549.23,5746.67 h60
  text "EXTERNAL" at 12281.46,5746.67 h60
  text "PER" at 10749.23,5636.55 h60
  text "IPC-D-275 CLASS 2 LEVEL C" at 10969.23,5636.54 h60
  text "MIL, HOLES" at 12457.46,5536.07 h60
  text "+/-" at 12065,5527.48 h60
  text "+/-" at 12919,5527.48 h60
  text "REGISTRATION TOLERANCES:" at 10549.23,5526.42 h60
  text "METAL" at 11749,5526.42 h60
  text "5" at 12325.2,5526.42 h60
  text "3" at 13158.2,5526.42 h60
  text "MIL" at 13274.46,5526.42 h60
  text "HOLE SIZE TOLERANCE (UNLESS OTHERWISE SPECIFIED):" at 10549.23,5428.1 h60
  text "+/-" at 12919,5425.23 h60
  text "3" at 13158.2,5424.17 h60
  text "MIL" at 13274.46,5424.17 h60
  text "MATERIAL:" at 10474.46,5286.52 h60
  text "FR-4 High Tg" at 11460.9,5158 h60
  text "X" at 11316.46,5150.01 h60
  text "FR-408" at 10895.46,5145.49 h60
  text "OTHER" at 12383.46,5145.49 h60
  text "62 MIL (1.6mm) +/-10%" at 11215.56,5002.46 h60
  text "X" at 11095.46,5000.01 h60
  text "THICKNESS:" at 10549.23,4994.24 h60
  text "OTHER" at 12500.46,4994.24 h60
  text "TOLERANCE:" at 10549.23,4855.92 h60
  text "X" at 11397.46,4855.92 h60
  text "ANSI IPC-6012 TYPE 3 CLASS 2" at 11575.48,4855.92 h60
  text "OTHER +/-" at 11575.46,4711.73 h60
  text "BOW & TWIST:" at 10549.23,4566.54 h60
  text "X" at 11397.46,4566.54 h60
  text "ANSI IPC-6012 TYPE 3 CLASS 2" at 11575.48,4566.54 h60
  text "OTHER +/-" at 11575.46,4419.85 h60
  text "DRILLING:" at 10474.46,4289.23 h60
  text "NC_DRILL FILES" at 12235.46,4184.04 h60
  text "REFERENCE:" at 10549.23,4180.1 h60
  text "X" at 11206.46,4180.01 h60
  text "AS SHOWN" at 11384.46,4180.1 h60
  text "X" at 12107.46,4180.1 h60
  text "OTHER" at 12533.46,4037.85 h60
  text "PTH COPPER THICKNESS:" at 10548.91,4034.32 h60
  text "X" at 11688.14,4034.32 h60
  text "20-30 um" at 11816.14,4034.32 h60
  text "BOARD FINISH:" at 10474.46,3886.73 h60
  text "SILKSCREEN:" at 10629.68,3776.6 h60
  text "X" at 11587.46,3776.6 h60
  text "TOP" at 11704.46,3776.6 h60
  text "X" at 12097.46,3776.6 h60
  text "BOTTOM" at 12215.46,3776.6 h60
  text "SILKSCREEN COLOR:" at 10629.68,3621.41 h60
  text "X" at 11586.46,3621.41 h60
  text "WHITE" at 11704.46,3621.41 h60
  text "OTHER" at 12215.46,3621.41 h60
  text "X" at 11717.46,3477.96 h60
  text "GREEN" at 11835.46,3477.96 h60
  text "OTHER" at 12453.46,3477.96 h60
  text "SOLDER RESIST COLOR:" at 10629.68,3471.1 h60
  text "X" at 11717.46,3323.71 h60
  text "MATTE" at 11835.46,3323.71 h60
  text "SEMI-GLOSS" at 12453,3323.07 h60
  text "IMMERSION GOLD (ENIG)" at 11535.46,3150.94 h60
  text "ENEPIG" at 12873,3143.72 h60
  text "SURFACE FINISH:" at 10474.46,3142.72 h60
  text "X" at 11357.46,3142.72 h60
  text "IMM. TIN/SILVER OR EQUIV" at 10804,3005.4 h60
  text "OTHER" at 12235.46,3001.47 h60
  text "ARRAY/PANEL:" at 10474.46,2846.09 h60
  text "CUT AND TRIM PER M1 BOARD OUTLINE" at 11535.46,2837.87 h60
  text "N.C. ROUTE" at 11535.46,2701.9 h60
  text "X" at 12223.46,2701.9 h60
  text "V. SCORE" at 12401.46,2701.9 h60
  text "CERTIFICATION:" at 10474.46,2572.77 h60
  text "MATERIALS AND WORKMANSHIP FOR ALL PCBS" at 11199.46,2572.77 h60
  text "TO MEET OR EXCEED THE REQUIREMENTS OF:" at 11199.46,2478.71 h60
  text "X" at 10836.97,2350.08 h60
  text "ANSI IPC-A-600F CLASS ->" at 10964.96,2350.08 h60
  text "X" at 12612.97,2350.08 h60
  text "2" at 12722.96,2350.08 h60
  text "1" at 12407.96,2348.58 h60
  text "3" at 13076.96,2348.58 h60
  text "X" at 11648.97,2202.39 h60
  text "RoHS" at 11776.96,2202.39 h60
  text "OTHER" at 12421.36,2202.39 h60
  text "PER ORDER" at 12818.42,2202.39 h60
  text "ALL BOARDS MUST MEET OR EXCEED UL94-V0 REQUIREMENTS." at 10502,2048.57 h60
  text "PCB MUST BEAR THE UL94V-0 UL REGISTERED MATERIAL ID NUMBER" at 10502,1932.5 h60
  text "ADDITIONAL REQUIREMENTS:" at 10474.46,1763.08 h60
  text "MICROSECTION:" at 10549.23,1655.95 h60
  text "YES" at 11454.96,1655.95 h60
  text "REQUIRED" at 12316.46,1511.62 h60
  text "BARE BOARD ELEC. TEST:" at 10549.23,1508.76 h60
  text "NONE" at 11854.96,1508.76 h60
  text "X" at 12198.46,1508.76 h60
  text "PER ORDER" at 12908.46,1508.76 h60
  text "XX MIL VIAS REQUIRE NON-CONDUCTIVE FILL AND PLANARIZE" at 10717.38,1303.82 h59
  text "XX MIL VIAS REQUIRE CONDUCTIVE FILL AND PLANARIZE" at 10725.38,1199.84 h60
  text "OUTER XX MIL TRACES REQUIRE 50 OHM SINGLE-ENDED IMPEDANCE" at 10724.39,1036.46 h58
  text "LAYER 2 & 3 (INNER LAYERS) XX MIL WIDE, XX MIL SPACE / TRACES REQUIRE 100 OHM DIFFERENTIAL IMPEDANCE" at 10716.39,800.74 h60
  text ".Layer_Name" at -282,-949.49 h60
M11 Gerber Information:
  lines w10: -1151,-1021.17 5449,-1021.17 ; -1151,-817.83 5451,-817.83 ; -1151,-614.5 -1151,-1224.5 2854,-1224.5 5451,-1224.5 5451,-614.5 -1150.5,-614.5 -1150.5,-1224.5 425,-1224.5 ; 1314,-1224.5 1314,-614.5 ; 2581,-817.83 2581,-614.5 ; 3421,-817.83 3421,-614.5 ; 4043,-1231 4043,-1028.17
  text "ALL ARTWORK VIEWED FROM TOP SIDE" at -1087.5,-746.67 h60
  text "BOARD #:" at 1389,-746.67 h60
  text ".PRJ_Number" at 1934.5,-746.67 h60
  text "REV:" at 2779,-746.67 h60
  text ".PCB_Rev" at 3070.5,-746.67 h60
  text "SVN REV:" at 3617,-746.67 h60
  text ".VersionControl_RevNumber" at 4123,-746.67 h60
  text "LAYER NAME =" at -1087.5,-949.49 h60
  text "TID #:" at 1389,-950 h60
  text ".TID" at 1934.5,-950 h60
  text "PLOT NAME =" at -1087.5,-1155.34 h60
  text ".plot_File_Name" at -282,-1155.34 h60
  text "GENERATED    :" at 1391,-1155.34 h60
  text ".Print_Date" at 2260.5,-1155.34 h60
  text ".Print_Time" at 2989.5,-1155.34 h60
  text "TEXAS INSTRUMENTS" at 4254,-1155.34 h60
M12 Stackup:
  drawing of 399 lines, arcs and shapes, not listed
  text "Layer" at 4501.09,7692 h60
  text "Name" at 4911,7692 h60
  text "Material" at 5850.74,7692 h60
  text "Thickness" at 6710.51,7692 h60
  text "Constant" at 7360.34,7692 h60
  text "Board Layer Stack" at 7930.2,7692 h60
  text "1" at 4501.09,7572 h60
  text "Top Overlay" at 4911,7572 h60
  text "2" at 4501.09,7452 h60
  text "Top Solder" at 4911,7452 h60
  text "Solder Resist" at 5850.74,7452 h60
  text "0.50mil" at 6710.51,7452 h60
  text "3.5" at 7360.34,7452 h60
  text "3" at 4501.09,7332 h60
  text "Top Layer" at 4911,7332 h60
  text "Copper" at 5850.74,7332 h60
  text "1.40mil" at 6710.51,7332 h60
  text "4" at 4501.09,7212 h60
  text "Dielectric 1" at 4911,7212 h60
  text "FR-4" at 5850.74,7212 h60
  text "7.00mil" at 6710.51,7212 h60
  text "4.2" at 7360.34,7212 h60
  text "5" at 4501.09,7092 h60
  text "Signal Layer 1" at 4911,7092 h60
  text "Copper" at 5850.74,7092 h60
  text "1.40mil" at 6710.51,7092 h60
  text "6" at 4501.09,6972 h60
  text "Dielectric 2" at 4911,6972 h60
  text "FR-4" at 5850.74,6972 h60
  text "14.00mil" at 6710.51,6972 h60
  text "4.2" at 7360.34,6972 h60
  text "7" at 4501.09,6852 h60
  text "Signal Layer 2" at 4911,6852 h60
  text "Copper" at 5850.74,6852 h60
  text "1.40mil" at 6710.51,6852 h60
  text "8" at 4501.09,6732 h60
  text "Dielectric 4" at 4911,6732 h60
  text "FR-4" at 5850.74,6732 h60
  text "11.00mil" at 6710.51,6732 h60
  text "4.2" at 7360.34,6732 h60
  text "9" at 4501.09,6612 h60
  text "Signal Layer 3" at 4911,6612 h60
  text "Copper" at 5850.74,6612 h60
  text "1.40mil" at 6710.51,6612 h60
  text "10" at 4501.09,6492 h60
  text "Dielectric 5" at 4911,6492 h60
  text "FR-4" at 5850.74,6492 h60
  text "14.00mil" at 6710.51,6492 h60
  text "4.2" at 7360.34,6492 h60
  text "11" at 4501.09,6372 h60
  text "Signal Layer 4" at 4911,6372 h60
  text "Copper" at 5850.74,6372 h60
  text "1.40mil" at 6710.51,6372 h60
  text "12" at 4501.09,6252 h60
  text "Dielectric 3" at 4911,6252 h60
  text "FR-4" at 5850.74,6252 h60
  text "7.00mil" at 6710.51,6252 h60
  text "4.2" at 7360.34,6252 h60
  text "13" at 4501.09,6132 h60
  text "Bottom Layer" at 4911,6132 h60
  text "Copper" at 5850.74,6132 h60
  text "1.40mil" at 6710.51,6132 h60
  text "14" at 4501.09,6012 h60
  text "Bottom Solder" at 4911,6012 h60
  text "Solder Resist" at 5850.74,6012 h60
  text "0.50mil" at 6710.51,6012 h60
  text "3.5" at 7360.34,6012 h60
  text "15" at 4501.09,5892 h60
  text "Bottom Overlay" at 4911,5892 h60
  text ".Layer_Name" at -282,-949.49 h60
M13 Component Bodies Top:
  text ".Layer_Name" at -282,-949.49 h60
M14 Component Bodies Bottom:
  text ".Layer_Name" at -282,-949.49 h60
M15 Courtyards Top:
  text ".Layer_Name" at -282,-949.49 h60
M16 Courtyards Bottom:
  text ".Layer_Name" at -282,-949.49 h60
Drill Drawing:
  circle w10: c4489.9,3012.54 r22.14
  lines w10: 4467.76,2591.91 4478.83,2591.91 4489.9,2602.98 4500.97,2591.91 4512.04,2591.91 4512.04,2602.98 4500.97,2614.05 4512.04,2625.11 4512.04,2636.18 4500.97,2636.18 4489.9,2625.11 4478.83,2636.18 4467.76,2636.18 4467.76,2625.11 4478.83,2614.05 4467.76,2602.98 4467.76,2591.91 ; 4467.76,2702.6 4467.76,2724.74 4478.83,2724.74 4478.83,2735.81 4500.97,2735.81 4500.97,2724.74 4512.04,2724.74 4512.04,2702.6 4500.97,2702.6 4500.97,2691.53 4478.83,2691.53 4478.83,2702.6 4467.76,2702.6 ; 4467.76,2813.29 4489.9,2835.43 4512.04,2813.29 4489.9,2791.15 4467.76,2813.29 ; 4467.76,2935.05 4489.9,2890.77 4512.04,2935.05 4467.76,2935.05 ; 4467.76,3090.02 4478.83,3112.16 4467.76,3134.3 4489.9,3123.23 4512.04,3134.3 4500.97,3112.16 4512.04,3090.02 4489.9,3101.09 4467.76,3090.02 ; 4467.76,3200.71 4478.83,3211.78 4467.76,3222.85 4478.83,3222.85 4489.9,3233.92 4500.97,3222.85 4512.04,3222.85 4500.97,3211.78 4512.04,3200.71 4500.97,3200.71 4489.9,3189.64 4478.83,3200.71 4467.76,3200.71
  lines w12: 4427,2562.02 7539.94,2562.02 ; 4427,3259.38 7539.94,3259.38 ; 4742.63,2462.4 4742.63,3359 ; 5059.82,2462.4 5059.82,3359 ; 5681.56,2462.4 5681.56,3359 ; 5925.88,2462.4 5925.88,3359 ; 6286.22,2462.4 6286.22,3359 ; 6995.73,2462.4 6995.73,3359 ; 4427,2462.4 4427,3359 7539.94,3359 7539.94,2462.4 4427,2462.4
  text "Symbol" at 4486.77,3289.26 h72
  text "Quantity" at 4772.52,3289.26 h72
  text "Finished Hole Size" at 5089.7,3289.26 h72
  text "Plated" at 5711.45,3289.26 h72
  text "Hole Type" at 5955.77,3289.26 h72
  text "Drill Layer Pair" at 6316.11,3289.26 h72
  text "Hole Tolerance" at 7025.62,3289.26 h72
  text "22" at 4772.52,3189.64 h60
  text "7.87mil (0.200mm)" at 5089.7,3189.64 h60
  text "PTH" at 5711.45,3189.64 h60
  text "Round" at 5955.77,3189.64 h60
  text "Top Layer - Bottom Layer" at 6316.11,3189.64 h60
  text "357" at 4772.52,3090.02 h60
  text "8.00mil (0.203mm)" at 5089.7,3090.02 h60
  text "PTH" at 5711.45,3090.02 h60
  text "Round" at 5955.77,3090.02 h60
  text "Top Layer - Bottom Layer" at 6316.11,3090.02 h60
  text "1" at 4772.52,2990.4 h60
  text "8.00mil (0.203mm)" at 5089.7,2990.4 h60
  text "PTH" at 5711.45,2990.4 h60
  text "Round" at 5955.77,2990.4 h60
  text "Top Layer - Bottom Layer" at 6316.11,2990.4 h60
  text "+16.00mil" at 7025.62,2990.4 h60
  text "105" at 4772.52,2890.77 h60
  text "16.00mil (0.406mm)" at 5089.7,2890.77 h60
  text "PTH" at 5711.45,2890.77 h60
  text "Round" at 5955.77,2890.77 h60
  text "Top Layer - Bottom Layer" at 6316.11,2890.77 h60
  text "179" at 4772.52,2791.15 h60
  text "28.00mil (0.711mm)" at 5089.7,2791.15 h60
  text "PTH" at 5711.45,2791.15 h60
  text "Round" at 5955.77,2791.15 h60
  text "Top Layer - Bottom Layer" at 6316.11,2791.15 h60
  text "5" at 4772.52,2691.53 h60
  text "30.00mil (0.762mm)" at 5089.7,2691.53 h60
  text "PTH" at 5711.45,2691.53 h60
  text "Round" at 5955.77,2691.53 h60
  text "Top Layer - Bottom Layer" at 6316.11,2691.53 h60
  text "4" at 4772.52,2591.91 h60
  text "125.00mil (3.175mm)" at 5089.7,2591.91 h60
  text "PTH" at 5711.45,2591.91 h60
  text "Round" at 5955.77,2591.91 h60
  text "Top Layer - Bottom Layer" at 6316.11,2591.91 h60
  text "673 Total" at 4772.52,2492.29 h60
  text ".Layer_Name" at -282,-949.49 h60
Mechanical 17:
  text ".Layer_Name" at -282,-949.49 h60
Mechanical 18:
  text ".Layer_Name" at -282,-949.49 h60
Mechanical 19:
  text ".Layer_Name" at -282,-949.49 h60

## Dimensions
0,0 to 3149,0 on M2 Board Dimensions
0,0 to 0,2999 on M2 Board Dimensions
-859,-491 to 141,-491 on M2 Board Dimensions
